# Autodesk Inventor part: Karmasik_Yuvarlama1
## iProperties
Created: 2009-12
Part Number: Karmasik_Yuvarlama1
Document SubType Name: Modeling
Designer: bulent
Density: 1 g/cm^3
Author: bulent
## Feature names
1. Extrusion1
2. Extrusion2
